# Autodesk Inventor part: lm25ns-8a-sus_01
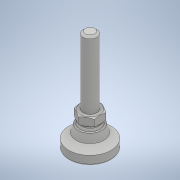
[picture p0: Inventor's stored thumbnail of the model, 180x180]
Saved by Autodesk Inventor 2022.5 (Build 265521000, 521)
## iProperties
Part Number: lm25ns-8a-sus_01
Material: 一般
Document SubType Name: Modeling
Designer: ImaoCorp
Density: 1 g/cm^3
Appearance: 既定
Author: ImaoCorp
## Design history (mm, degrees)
feature "lm25ns-8a-sus_01"
node "ソリッド1"
